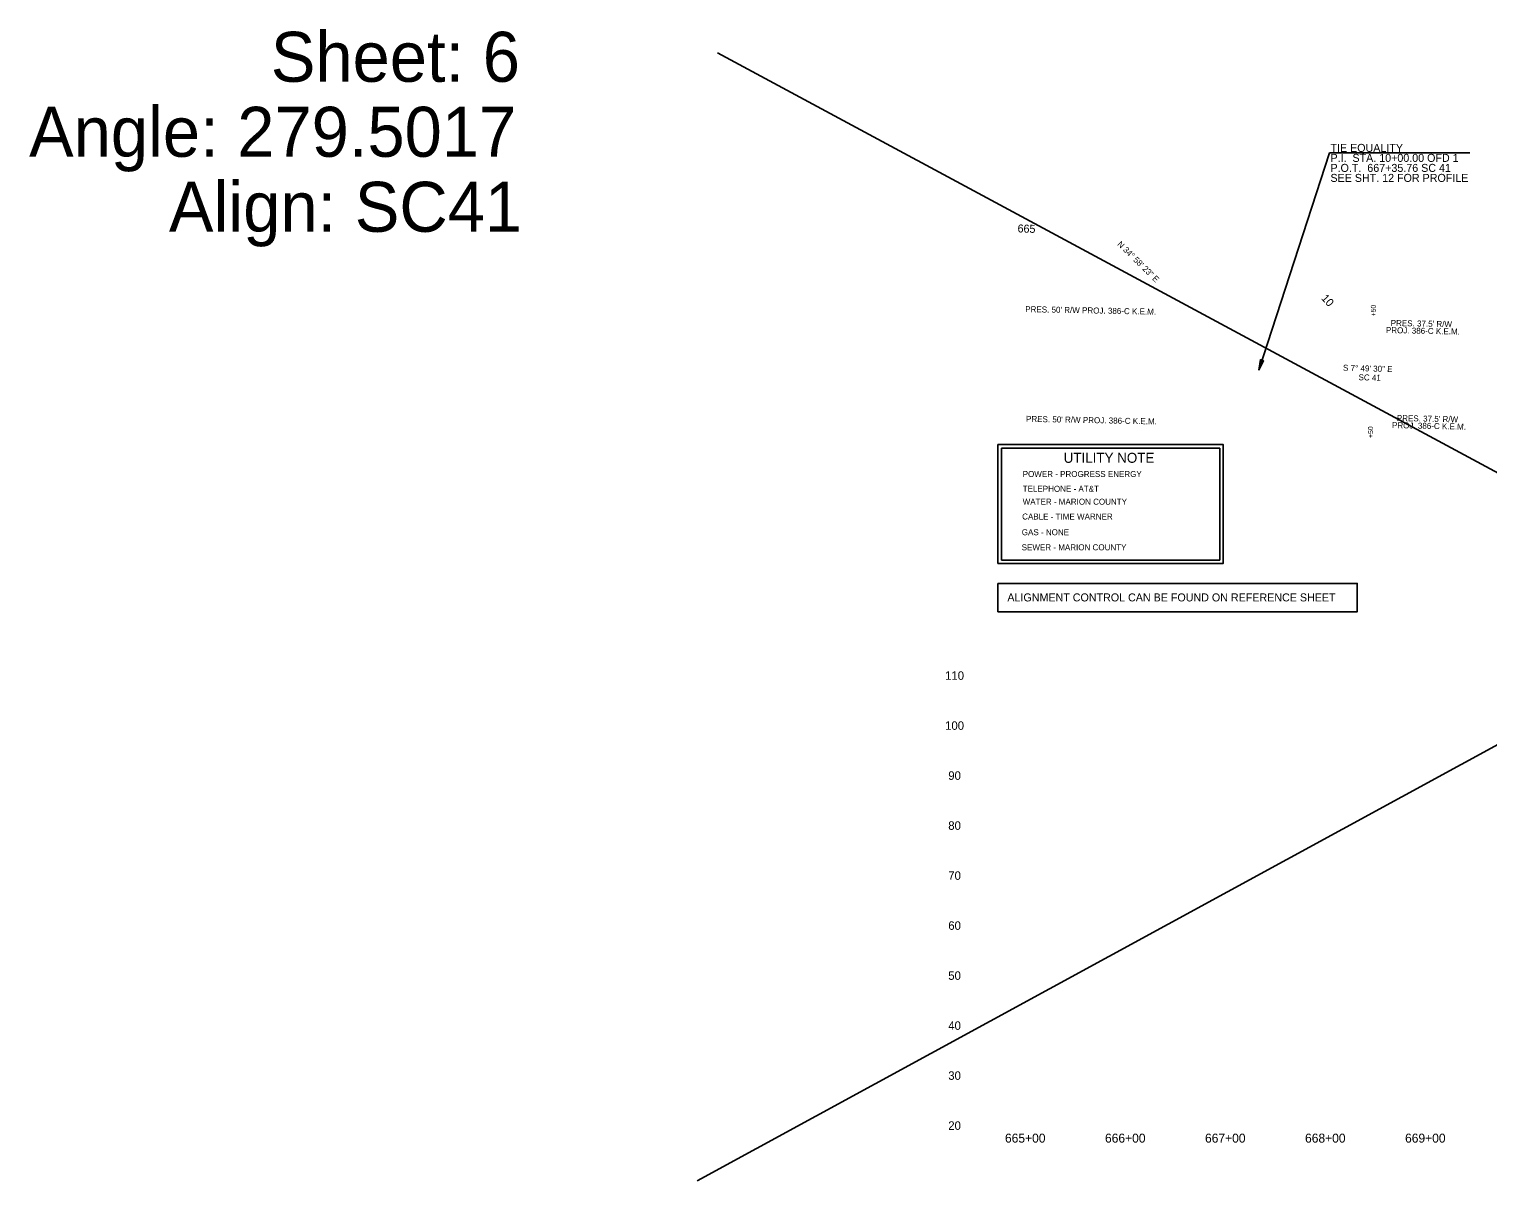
# Model space of a CAD drawing. Extents: x 2522404 to 2525275, y 885432 to 893540.
# Drawn here: x 2522419 to 2523877, y 886638 to 887790 of the extents above; entities that cross this region are included whole.
import ezdxf

# ---------------------------------------------------------------- set-up
doc = ezdxf.new("R2010")
doc.units = 0
for name, color, linetype in [('Default', 7, 'Continuous'), ('GN_Clip', 7, 'Continuous'), ('RD_DDB_ElevTX', 7, 'Continuous'), ('RD_DDB_Profile_EX', 7, 'Continuous'), ('RD_DDB_Profile_PR', 7, 'Continuous'), ('RD_EX_Misc', 7, 'Continuous'), ('RD_HC_Cl', 7, 'Continuous'), ('RD_HC_TX_Sta50', 7, 'Continuous'), ('RD_PD_Final_LnLine', 7, 'Continuous'), ('RD_PD_RW_TX', 7, 'Continuous'), ('RD_SHT_IplotShp', 7, 'Continuous')]:
    doc.layers.add(name, color=color, linetype=linetype)

# ---------------------------------------------------------------- blocks, each defined once
blk = doc.blocks.new('AH4_')
at = {"layer": 'Default'}
blk.add_lwpolyline([(0, 0), (-10.4, 1.5), (-8.8, 0), (-10.4, -1.5)], close=True, dxfattribs=at)

msp = doc.modelspace()

# ---------------------------------------------------------------- linework, layer by layer
at = {"layer": 'RD_DDB_ElevTX'}
for p, q in [((2523107.1, 887765.8), (2525164, 886658.3)), ((2523086.7, 886637.9), (2525137.9, 887755.9))]:
    msp.add_line(p, q, dxfattribs=at)
at = {"layer": 'RD_DDB_Profile_PR'}
msp.add_lwpolyline([(2523387.6, 887235.3), (2523387.6, 887206.9), (2523746.8, 887206.9), (2523746.8, 887235.3)], close=True, dxfattribs=at)
at = {"layer": 'RD_EX_Misc'}
for points in [[(2523407.7, 887255.3), (2523387.6, 887255.3), (2523387.6, 887374.1), (2523612.9, 887374.1), (2523612.9, 887255.3), (2523407.7, 887255.3)], [(2523411.3, 887258.7), (2523391.2, 887258.7), (2523391.2, 887370.4), (2523609.3, 887370.4), (2523609.3, 887258.7), (2523411.3, 887258.7)]]:
    msp.add_lwpolyline(points, dxfattribs=at)
at = {"layer": 'RD_PD_RW_TX'}
for p, q in [((2523648.3, 887448.7), (2523719.1, 887666)), ((2523719.1, 887666), (2523859.5, 887666))]:
    msp.add_line(p, q, dxfattribs=at)

# ---------------------------------------------------------------- block references
at = {"layer": 'RD_PD_Final_LnLine', "rotation": -108.31435027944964}
msp.add_blockref('AH4_', (2523648.3, 887448.7), dxfattribs=at)

# ---------------------------------------------------------------- texts
at = {"layer": 'GN_Clip'}
for s, p in [('665+00', (2523394.6, 886676.1)), ('666+00', (2523494.6, 886676.1)), ('667+00', (2523594.6, 886676.1)), ('668+00', (2523694.6, 886676.1)), ('669+00', (2523794.6, 886676.1))]:
    msp.add_text(s, height=9, dxfattribs=at).set_placement(p)
at = {"layer": 'RD_DDB_Profile_EX'}
for s, rotation, p in [('665', 358.3234, (2523407.1, 887586.3)), ('10', 312.6086, (2523710.3, 887520.1))]:
    msp.add_text(s, height=8, rotation=rotation, dxfattribs=at).set_placement(p)
at = {"layer": 'RD_DDB_Profile_PR'}
msp.add_text('ALIGNMENT CONTROL CAN BE FOUND ON REFERENCE SHEET', height=8, dxfattribs=at).set_placement((2523397, 887217.3))
at = {"layer": 'RD_EX_Misc'}
for s, height, p in [('Sheet: 6', 50, (2522660.6, 887736.9)), ('Angle: 279.5017', 50, (2522418.9, 887661.9)), ('Align: SC41', 50, (2522558.7, 887586.9)), ('UTILITY NOTE', 10, (2523453.3, 887355.9)), ('POWER - PROGRESS ENERGY', 6, (2523412.3, 887341.7)), ('TELEPHONE - AT&T', 6, (2523412.3, 887326.9)), ('WATER - MARION COUNTY', 6, (2523412.3, 887314)), ('CABLE - TIME WARNER', 6, (2523411.8, 887299.2)), ('GAS - NONE', 6, (2523411.4, 887283.5)), ('SEWER - MARION COUNTY', 6, (2523411.3, 887268.4))]:
    msp.add_text(s, height=height, dxfattribs=at).set_placement(p)
at = {"layer": 'RD_HC_Cl'}
for s, height, rotation, p in [('TIE EQUALITY', 8, 360, (2523720, 887666.8)), ('P.I.  STA. 10+00.00 OFD 1', 8, 360, (2523720, 887656.8)), ('SEE SHT. 12 FOR PROFILE', 8, 360, (2523720, 887636.8)), ('P.O.T.  667+35.76 SC 41', 8, 360, (2523720, 887646.8)), ('N 34%%d 58\' 23" E', 6, 315.5254, (2523506.4, 887573.9)), ('S 7%%d 49\' 30" E', 6, 358.3234, (2523732.5, 887448)), ('SC 41 ', 6, 358.3234, (2523748, 887438.5))]:
    msp.add_text(s, height=height, rotation=rotation, dxfattribs=at).set_placement(p)
at = {"layer": 'RD_HC_TX_Sta50'}
for s, p in [('110', (2523334.7, 887138.9)), ('100', (2523334.7, 887088.9)), ('90', (2523337.9, 887038.9)), ('80', (2523337.9, 886988.9)), ('70', (2523337.9, 886938.9)), ('60', (2523337.9, 886888.9)), ('50', (2523337.9, 886838.9)), ('40', (2523337.9, 886788.9)), ('30', (2523337.9, 886738.9)), ('20', (2523337.9, 886688.9))]:
    msp.add_text(s, height=8.5, dxfattribs=at).set_placement(p)
at = {"layer": 'RD_SHT_IplotShp'}
for s, height, rotation, p in [("PRES. 50' R/W PROJ. 386-C K.E.M.", 6, 358.8484, (2523414.8, 887506.6)), ('+50', 5, 90, (2523765.4, 887502.3)), ("PRES. 37.5' R/W", 6, 358.7818, (2523780.2, 887492.8)), ('PROJ. 386-C K.E.M.', 6, 358.7818, (2523775.4, 887485.7)), ("PRES. 50' R/W PROJ. 386-C K.E.M.", 6, 358.8484, (2523415.6, 887396.9)), ('PROJ. 386-C K.E.M.', 6, 358.7818, (2523781.5, 887390.6)), ("PRES. 37.5' R/W", 6, 358.7818, (2523786.3, 887397.7)), ('+50', 5, 90, (2523762.6, 887380.7))]:
    msp.add_text(s, height=height, rotation=rotation, dxfattribs=at).set_placement(p)

doc.saveas('drawing.dxf')
